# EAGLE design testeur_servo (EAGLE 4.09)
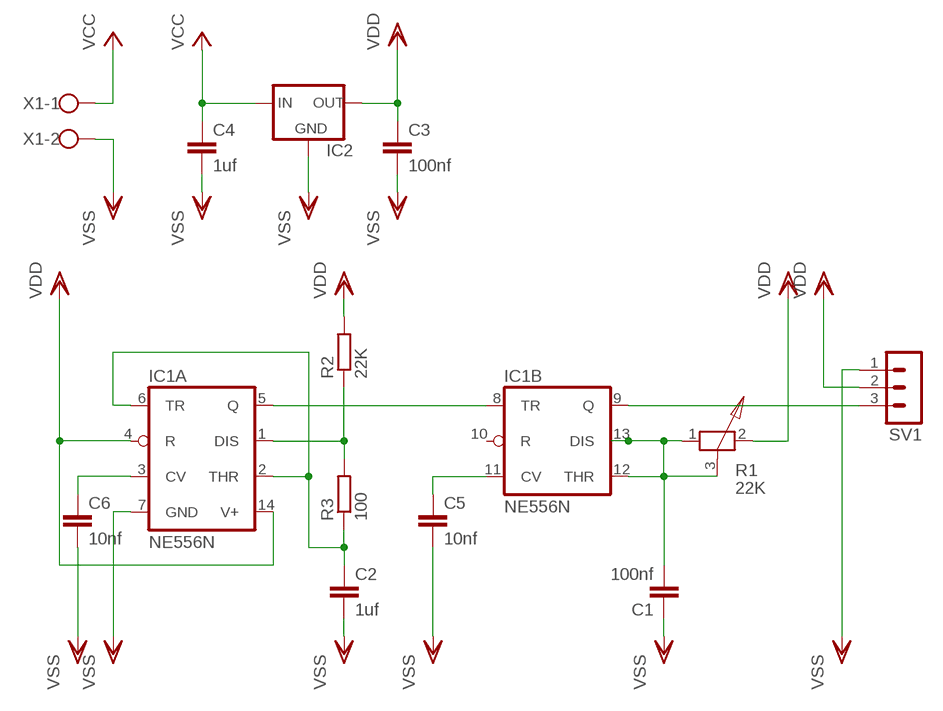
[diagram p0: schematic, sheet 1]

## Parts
C1  100nf  C-EU050-025X075  [C050-025X075]
C2  1uf  C-EU025-024X044  [C025-024X044]
C3  100nf  C-EU050-025X075  [C050-025X075]
C4  1uf  C-EU025-024X044  [C025-024X044]
C5  10nf  C-EU050-025X075  [C050-025X075]
C6  10nf  C-EU050-025X075  [C050-025X075]
IC1  NE556N  [DIL14]
IC2  78XXL  [78XXL]
R1  22K  POT-L  [PT-10]
R2  22K  R-EU_0204/7  [0204/7]
R3  100  R-EU_0204/7  [0204/7]
SV1  MA03-1  [MA03-1]
X1  AK500/2  [AK500/2]

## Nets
N$1: IC1.1(A:DIS) R2.1 R3.2
N$2: C6.1 IC1.3(A:CV)
N$4: C2.1 IC1.2(A:THR) IC1.6(A:TR) R3.1
N$5: C5.1 IC1.11(B:CV)
N$9: IC1.5(A:Q) IC1.8(B:TR)
N$11: C1.2 IC1.12(B:THR) IC1.13(B:DIS) R1.1 R1.3
N$15: IC1.9(B:Q) SV1.3
VCC: C4.1 IC2.IN X1.1
VDD: C3.1 IC1.4(A:R) IC1.14(A:V+) IC2.OUT R1.2 R2.2 SV1.2
VSS: C1.1 C2.2 C3.2 C4.2 C5.2 C6.2 IC1.7(A:GND) IC2.GND SV1.1 X1.2
Unconnected: IC1.10(B:R)

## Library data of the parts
C1-C6 = rcl:C-EU: CAPACITOR, European symbol
IC1 = linear:*556: Dual TIMER
IC2 = v-reg:78XXL: VOLTAGE REGULATOR
R1 = discrete:POT-L
R2 R3 = rcl:R-EU_: RESISTOR, European symbol
SV1 = con-lstb:MA03-1: PIN HEADER
X1 = con-ptr500:AK500/2: CONNECTOR

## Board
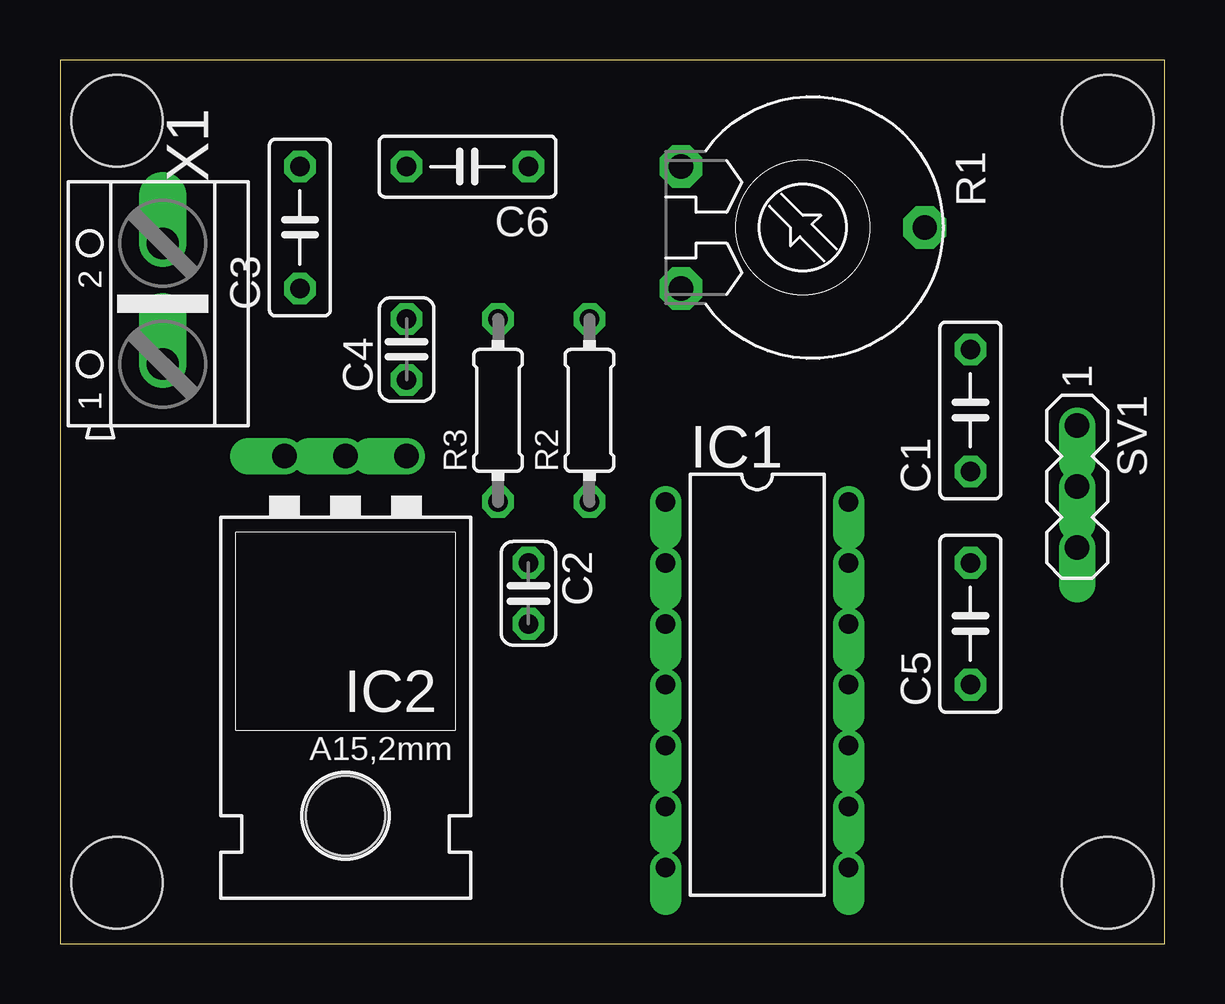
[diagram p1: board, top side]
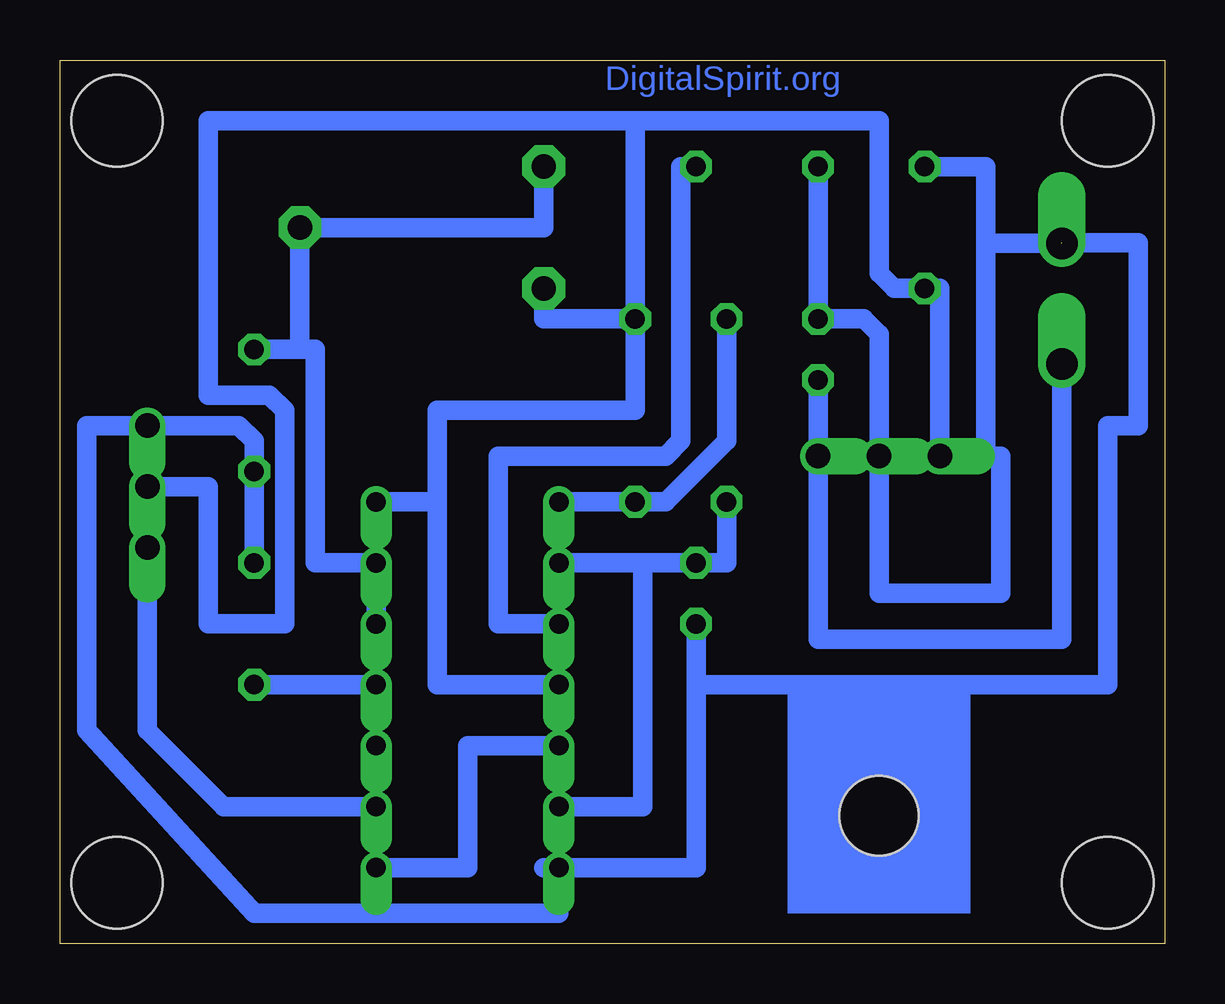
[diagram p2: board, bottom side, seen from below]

Size 46.02 x 36.82 mm. Coordinates in mm from the lower left corner, seen from the top.
Outline: 0,0 46.02,0 46.02,36.82 0,36.82 0,0
Copper layers used: Bottom
Holes 3.81 mm at 2.38,34.29 2.38,2.54 43.65,2.54 43.65,34.29

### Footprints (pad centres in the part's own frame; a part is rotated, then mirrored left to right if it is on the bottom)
C050-025X075 = drill 0.813 octagon: 1 -2.54,0; 2 2.54,0
C025-024X044 = drill 0.813 octagon: 1 -1.27,0; 2 1.27,0
DIL14 = drill 0.813 offset: 1 -7.62,-3.81; 2 -5.08,-3.81; 3 -2.54,-3.81; 4 0,-3.81; 5 2.54,-3.81; 6 5.08,-3.81; 7 7.62,-3.81; 8 7.62,3.81; 9 5.08,3.81; 10 2.54,3.81; 11 0,3.81; 12 -2.54,3.81; 13 -5.08,3.81; 14 -7.62,3.81
78XXL = drill 1.016 offset: GND 0,-3.81; IN -2.54,-3.81; OUT 2.54,-3.81 | hole 3.302: 0,11.176
PT-10 = drill 1.016 pad 1.778 octagon: 1 -2.54,-5.08; 2 2.54,-5.08; 3 0,5.08
0204/7 = drill 0.813 octagon: 1 -3.81,0; 2 3.81,0
MA03-1 = drill 1.016 offset: 1 -2.54,0; 2 0,0; 3 2.54,0
AK500/2 = drill 1.321 offset: 1 -2.515,0; 2 2.515,0

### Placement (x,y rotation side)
C1  37.93,22.22 90 top
C2  19.52,14.6 270 top
C3  10,29.84 90 top
C4  14.44,24.76 90 top
C5  37.93,13.33 90 top
C6  16.98,32.38 180 top
IC1  29.05,10.79 270 top
IC2  11.9,16.5 180 top
R1  30.95,29.84 270 top
R2  22.06,22.22 90 top
R3  18.25,22.22 90 top
SV1  42.38,19.04 270 top
X1  4.28,26.66 90 top

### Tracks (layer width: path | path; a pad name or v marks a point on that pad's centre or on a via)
N$1
  Bottom 0.813: IC1.1 R2.1 20.79,18.41 18.25,20.95 R3.2
N$2
  Bottom 0.813: C6.1 20.16,32.38 20.16,20.95 20.79,20.31 27.78,20.31 27.78,13.33 IC1.3
N$4
  Bottom 0.813: 21.74,15.87 21.74,5.71 IC1.6 | R3.1 18.25,15.87 C2.1 21.74,15.87 | 21.74,15.87 IC1.2
N$5
  Bottom 0.813: IC1.11 C5.1
N$9
  Bottom 0.813: IC1.5 29.05,8.25 29.05,3.17 IC1.8
N$11
  Bottom 0.813: IC1.12 IC1.13 35.39,15.87 35.39,24.76 36.03,24.76 | 36.03,24.76 C1.2 | R1.1 25.87,29.84 R1.3 36.03,24.76
N$15
  Bottom 0.813: SV1.3 42.38,8.89 39.2,5.71 IC1.9
VCC
  Bottom 0.813: X1.1 4.28,12.7 14.44,12.7 IC2.IN C4.1
VDD
  Bottom 0.813: 22.06,34.29 R2.2 | 22.06,34.29 11.9,34.29 11.9,27.93 11.27,27.3 C3.1 9.36,27.3 IC2.OUT | IC1.4 30.32,10.79 30.32,18.41 | 30.32,18.41 30.32,22.22 22.06,22.22 R2.2 | 30.32,18.41 IC1.14 | R1.2 25.87,26.03 R2.2 | SV1.2 39.84,19.04 39.84,13.33 36.66,13.33 36.66,22.22 37.3,22.86 39.84,22.86 39.84,34.29 22.06,34.29
VSS  (1 unrouted)
  Bottom 0.813: 7.46,29.18 X1.2 | 7.46,29.18 7.46,20.31 6.82,20.31 6.82,14.6 11.9,14.6 IC2.GND 11.9,25.39 12.54,26.03 C4.2 C6.2 | 7.46,29.18 7.46,32.38 C3.2 | 4.28,29.2 1.1,29.2 1.1,21.58 2.38,21.58 2.38,10.79 19.52,10.79 C2.2 19.52,3.17 IC1.7 | IC1.7 25.87,3.17 | C5.2 C1.1 37.93,20.95 38.57,21.58 SV1.1 44.92,21.58 44.92,14.6 | IC1.7 25.23,1.27 37.93,1.27 44.92,8.89 44.92,14.6 | 44.92,13.97 44.92,14.6
(copper drawn outside any net)
  shapes: Bottom area x1

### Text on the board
Bottom: DigitalSpirit.org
